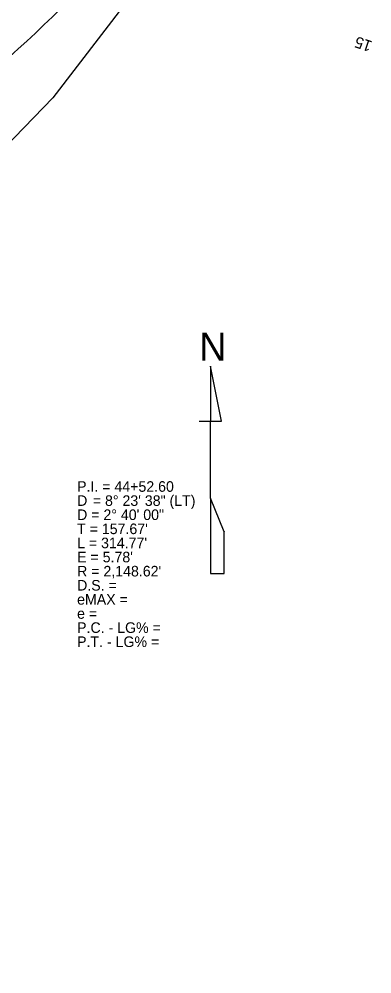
# Model space of a CAD drawing. Extents: x 2500794 to 2511032, y 910653 to 917533.
# Drawn here: x 2505814 to 2506064, y 912701 to 913378 of the extents above; entities that cross this region are included whole.
import ezdxf

# ---------------------------------------------------------------- set-up
doc = ezdxf.new("R2010")
doc.units = 0
for name, color, linetype in [('Default', 7, 'Continuous'), ('RD_EX_H2O_WetLd', 7, 'Continuous'), ('RD_EX_Misc', 7, 'Continuous'), ('RD_HC_Data', 7, 'Continuous'), ('RD_HC_TX_Sta50', 7, 'Continuous'), ('RD_Sketch9', 7, 'Continuous')]:
    doc.layers.add(name, color=color, linetype=linetype)

# ---------------------------------------------------------------- blocks, each defined once
blk = doc.blocks.new('Wetlands')
at = {"layer": 'Default'}
blk.add_lwpolyline([(636504.63, 232012.42), (636482.69, 231983.86), (636453.25, 231953.44), (636428.85, 231929.82), (636373.86, 231876.59), (636322.7, 231826.15)], dxfattribs=at)

msp = doc.modelspace()

# ---------------------------------------------------------------- linework, layer by layer
at = {"layer": 'RD_EX_Misc'}
for p, q in [((2505956.97, 913092.99), (2505949.13, 913132.19)), ((2505949.13, 913132.19), (2505949.13, 913132.19)), ((2505949.13, 913132.19), (2505949.13, 913092.99)), ((2505941.29, 913092.99), (2505949.13, 913092.99)), ((2505949.13, 913038.6), (2505949.13, 913092.99)), ((2505949.13, 913092.99), (2505956.97, 913092.99)), ((2505956.97, 913092.99), (2505956.97, 913093.46)), ((2505958.93, 913014.59), (2505949.13, 913038.6)), ((2505949.13, 913038.6), (2505949.13, 912985.19)), ((2505958.93, 912985.19), (2505958.93, 913014.86)), ((2505958.93, 913014.86), (2505958.93, 913014.59)), ((2505949.13, 912985.19), (2505958.93, 912985.19))]:
    msp.add_line(p, q, dxfattribs=at)
at = {"layer": 'RD_Sketch9'}
msp.add_arc((2504883.09, 914369.79), 1375, 311.51065, 322.60071, dxfattribs=at)

# ---------------------------------------------------------------- block references
at = {"layer": 'Default', "xscale": 3.937007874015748, "yscale": 3.937007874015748}
msp.add_blockref('Wetlands', (0, 0), dxfattribs=at)
at = {"layer": 'RD_EX_H2O_WetLd', "xscale": 3.937007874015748, "yscale": 3.937007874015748}
msp.add_blockref('Wetlands', (0, 0), dxfattribs=at)

# ---------------------------------------------------------------- texts
at = {"layer": 'RD_EX_Misc'}
msp.add_text('N', height=20, dxfattribs=at).set_placement((2505941.24, 913135.9))
at = {"layer": 'RD_HC_Data'}
for s, p in [('P.I. = 44+52.60', (2505854.67, 913043.05)), ('D', (2505854.67, 913033.05)), ('    = 8%%d 23\' 38" (LT)', (2505854.67, 913033.05)), ('D = 2%%d 40\' 00"', (2505854.67, 913023.05)), ("T = 157.67'", (2505854.67, 913013.05)), ("L = 314.77'", (2505854.67, 913003.05)), ("E = 5.78'", (2505854.67, 912993.05)), ("R = 2,148.62'", (2505854.67, 912983.05)), ('D.S. = ', (2505854.67, 912973.05)), ('eMAX = ', (2505854.67, 912963.05)), ('e = ', (2505854.67, 912953.05)), ('P.C. - LG% = ', (2505854.67, 912943.05)), ('P.T. - LG% = ', (2505854.67, 912933.05))]:
    msp.add_text(s, height=7.5, dxfattribs=at).set_placement(p)
at = {"layer": 'RD_HC_TX_Sta50'}
msp.add_text('15', height=8, rotation=161.46, dxfattribs=at).set_placement((2506064.44, 913362.16))

doc.saveas('drawing.dxf')
